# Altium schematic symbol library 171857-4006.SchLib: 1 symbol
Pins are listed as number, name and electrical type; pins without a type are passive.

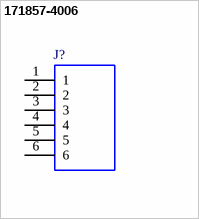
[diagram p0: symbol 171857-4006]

## 171857-4006
designator J?
Headers & Wire Housings KK RPC 254 Hdr FrLk R/A 06 Ckt 15Au T&R; Manufacturer_Name: Molex; Geometry.Height: 6.35mm
footprint HDRRA6W94P0X254_1X6_1509X318X635P
pins: 1, 2, 3, 4, 5, 6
